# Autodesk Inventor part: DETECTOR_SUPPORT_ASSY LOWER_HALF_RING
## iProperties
Shininess: 64.0
Length Units: 11272
Angle Units: 11279
Time Units: 11290
Mass Units: 11286
Length Display Precision: 3
Angle Display Precision: 2
Compacted: True
Part Number: DETECTOR_SUPPORT_ASSY LOWER_HALF_RING
Document SubType Name: Modeling
Created: 2004-08
Designer: John Blackburn
Material: ALUMINUM
Manufacturer: Standard
Standards Organization: Custom
Density: 0.0
Volumn: 0.0
Area: 0.0
PropertySet Name: Model Information
Control State: 0
Master: False
Checked Out: False
Author: John Blackburn
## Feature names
1. ExtrusionBlind1
2. AM_HOLE_SI0029_1 [Hole]
3. AM_HOLE_SI0029_2 [Hole]
4. Polar Pattern1 [Circular Pattern]
5. AM_HOLE_SI0029_3 [Hole]
6. AM_HOLE_SI0029_4 [Hole]
7. AM_HOLE_SI0029_5 [Hole]
8. AM_HOLE_SI0029_6 [Hole]
9. Hole1
10. Hole2
11. Hole3
12. Hole4
13. Hole5
14. Hole6
15. Hole7
16. Hole8
17. Hole9
18. Hole10
19. Hole11
20. Hole12
21. Hole13
22. Hole14
23. Hole15
24. Hole16
25. Hole17
26. Hole18
27. Hole19
28. Hole20
29. ExtrusionThru1
30. ExtrusionThru2
31. Hole21
32. Rectangular Pattern1
33. Hole22
34. Rectangular Pattern2
35. Hole29
36. Hole30
